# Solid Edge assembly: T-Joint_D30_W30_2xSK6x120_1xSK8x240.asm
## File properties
Author: fknapp
Template: iso metric assembly.asm
Last saved by: fknapp
Revision: 6
Application: Solid Edge
Username: fknapp
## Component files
T-Joint_D30_W30.par
SK Knapp Schraube 8x240_ohne_Gewinde_22042020.par
SK Schraube 6x120_ohne_Gewinde.par
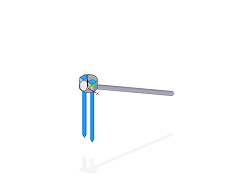
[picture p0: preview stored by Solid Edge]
